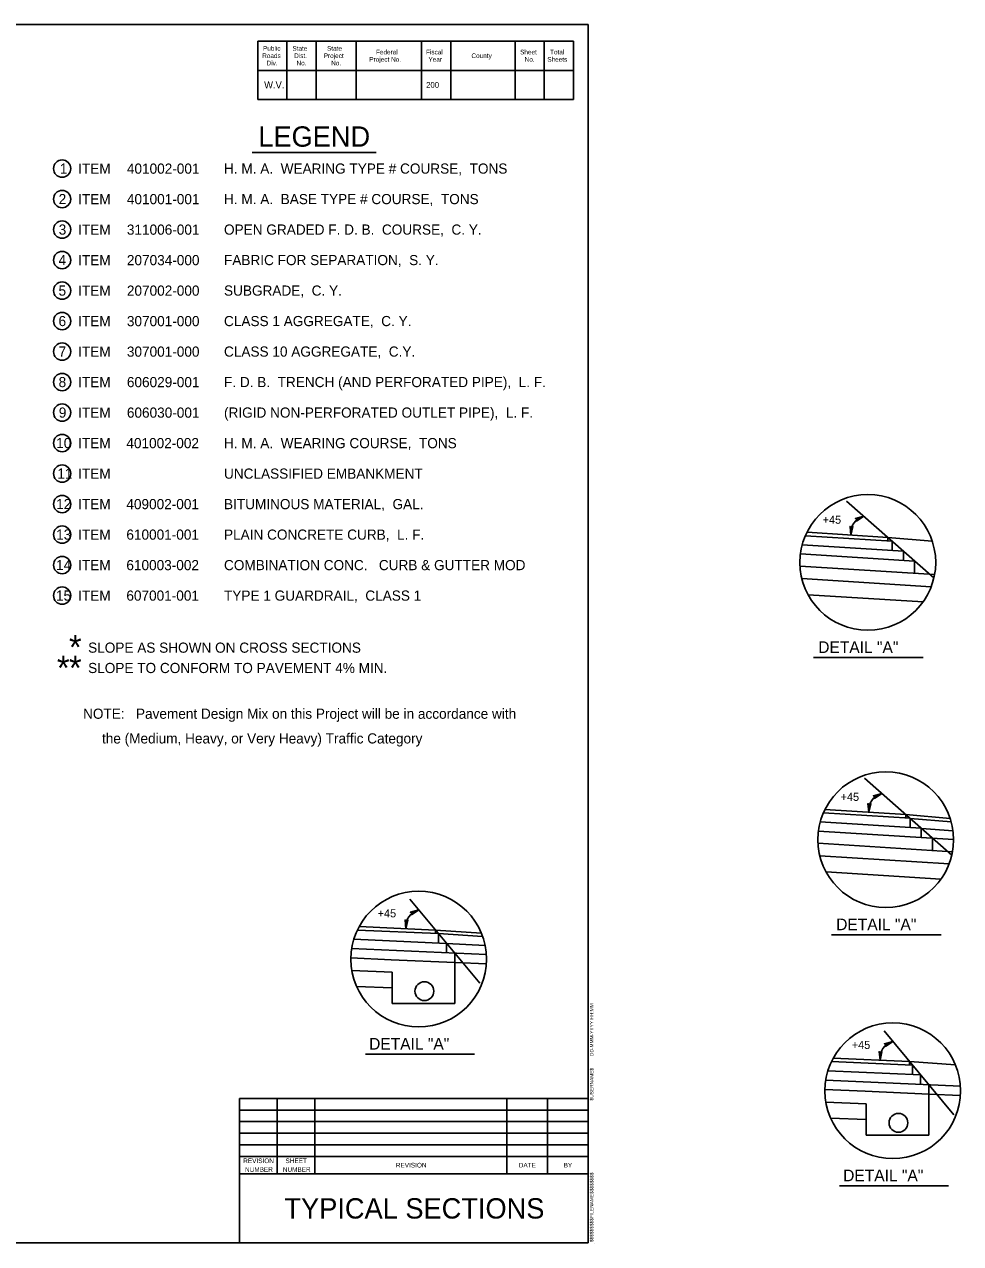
# Model space of a CAD drawing. Extents: x -540 to 1231, y -564 to 421.
# Drawn here: x 115.3 to 276.4, y -562.5 to -352.7 of the extents above; entities that cross this region are included whole.
import ezdxf

# ---------------------------------------------------------------- set-up
doc = ezdxf.new("R2010")
doc.units = 0
doc.layers.add('1', color=7, linetype='Continuous')
doc.layers.add('Des_ Drain_ Ftrs', color=7, linetype='Continuous')

msp = doc.modelspace()

# ---------------------------------------------------------------- linework, layer by layer
at = {"layer": '1'}
for p, q in [((212.32, -352.66), (-107.68, -352.66)), ((212.32, -352.66), (212.32, -562.42)), ((212.32, -352.66), (212.32, -352.66)), ((155.48, -355.54), (155.48, -365.6)), ((209.82, -355.54), (155.48, -355.54)), ((160.51, -355.54), (160.51, -365.6)), ((165.54, -355.54), (165.54, -365.6)), ((172.43, -355.54), (172.43, -365.6)), ((183.65, -355.54), (183.65, -365.6)), ((188.69, -355.54), (188.69, -365.6)), ((199.76, -355.54), (199.76, -365.6)), ((204.79, -355.54), (204.79, -365.6)), ((209.82, -355.54), (209.82, -365.6)), ((209.82, -360.58), (155.48, -360.58)), ((209.82, -365.6), (155.48, -365.6)), ((154.51, -374.73), (175.88, -374.73)), ((271.83, -447.95), (256.82, -434.73)), ((264.63, -441.61), (249.74, -440.68)), ((263.9, -440.97), (250, -440.1)), ((266.58, -443.33), (249.19, -442.23)), ((263.9, -441.57), (263.9, -440.97)), ((271.56, -441.65), (263.9, -440.97)), ((264.63, -441.61), (264.63, -443.21)), ((268.52, -445.04), (248.88, -443.81)), ((266.58, -443.33), (266.58, -444.92)), ((271.95, -447.36), (248.8, -445.9)), ((268.52, -445.04), (268.52, -447.15)), ((271.37, -449.46), (249.12, -448.07)), ((269.96, -452.08), (250.19, -450.84)), ((251.13, -461.65), (269.97, -461.65)), ((274.92, -495.67), (259.9, -482.45)), ((267.72, -489.33), (252.83, -488.39)), ((266.99, -488.69), (253.09, -487.82)), ((266.99, -489.28), (266.99, -488.68)), ((274.64, -489.37), (266.99, -488.68)), ((269.66, -491.05), (252.28, -489.95)), ((267.72, -489.33), (267.72, -490.92)), ((274.81, -489.93), (267.73, -489.34)), ((269.66, -491.05), (269.66, -492.64)), ((275.12, -491.47), (269.69, -491.07)), ((275.22, -492.99), (251.97, -491.53)), ((271.61, -492.76), (271.61, -494.86)), ((275.04, -495.08), (251.89, -493.62)), ((274.45, -497.18), (252.21, -495.78)), ((273.05, -499.8), (253.27, -498.56)), ((193.7, -517.72), (181.68, -503.26)), ((186.57, -509.18), (172.63, -508.57)), ((186.08, -508.56), (172.93, -507.98)), ((186.08, -509.16), (186.08, -508.56)), ((193.97, -509.13), (186.08, -508.56)), ((186.57, -509.18), (186.57, -510.81)), ((194.18, -509.68), (186.57, -509.18)), ((254.22, -509.37), (273.06, -509.37)), ((194.82, -512.77), (171.64, -511.76)), ((187.99, -510.86), (172.01, -510.16)), ((187.98, -510.86), (187.98, -512.47)), ((194.61, -511.22), (187.98, -510.86)), ((178.42, -513.68), (171.5, -513.37)), ((189.39, -514.15), (178.42, -513.68)), ((189.39, -512.54), (189.39, -514.15)), ((189.39, -521.23), (189.39, -514.15)), ((194.82, -514.39), (189.39, -514.15)), ((178.61, -515.84), (171.67, -515.54)), ((178.61, -521.23), (178.61, -515.84)), ((178.61, -515.84), (178.61, -515.84)), ((178.61, -518.54), (172.49, -518.27)), ((178.61, -521.23), (189.39, -521.23)), ((275.27, -540.38), (263.26, -525.92)), ((174.01, -529.94), (192.79, -529.94)), ((267.65, -531.21), (254.5, -530.64)), ((269.56, -533.51), (253.58, -532.82)), ((268.15, -531.83), (254.2, -531.22)), ((267.65, -531.81), (267.65, -531.21)), ((275.55, -531.78), (267.65, -531.21)), ((268.15, -531.83), (268.15, -533.46)), ((276.4, -535.43), (253.22, -534.42)), ((269.55, -533.51), (269.55, -535.12)), ((270.96, -535.19), (270.96, -536.81)), ((259.99, -536.33), (253.08, -536.03)), ((270.96, -536.81), (259.99, -536.33)), ((270.96, -543.89), (270.96, -536.81)), ((276.4, -537.05), (270.96, -536.81)), ((152.32, -562.54), (152.32, -537.55)), ((212.32, -537.55), (152.32, -537.55)), ((158.82, -550.54), (158.82, -537.55)), ((165.33, -550.54), (165.33, -537.55)), ((198.32, -550.54), (198.32, -537.55)), ((205.32, -550.54), (205.32, -537.55)), ((212.32, -562.42), (212.32, -537.55)), ((260.18, -538.5), (253.24, -538.2)), ((260.18, -543.89), (260.18, -538.5)), ((260.18, -538.5), (260.18, -538.5)), ((212.32, -539.55), (152.32, -539.55)), ((260.18, -541.19), (254.06, -540.93)), ((212.32, -541.54), (152.32, -541.54)), ((212.32, -543.55), (152.32, -543.55)), ((212.32, -545.54), (152.32, -545.54)), ((260.18, -543.89), (270.96, -543.89)), ((212.32, -547.54), (152.32, -547.54)), ((212.32, -550.54), (152.32, -550.54)), ((255.58, -552.6), (274.36, -552.6)), ((212.32, -562.42), (-107.68, -562.42)), ((212.32, -562.42), (212.32, -562.42)), ((213.42, -562.54), (213.42, -562.54)), ((213.42, -562.54), (213.42, -562.54))]:
    msp.add_line(p, q, dxfattribs=at)
for centre, radius in [((121.83, -377.49), 1.49), ((121.83, -382.74), 1.49), ((121.83, -387.99), 1.49), ((121.83, -393.24), 1.49), ((121.83, -398.49), 1.49), ((121.83, -403.74), 1.49), ((121.83, -408.99), 1.49), ((121.83, -414.24), 1.49), ((121.83, -419.49), 1.49), ((121.83, -424.74), 1.49), ((121.83, -429.99), 1.49), ((121.83, -435.24), 1.49), ((260.46, -445.29), 11.68), ((121.83, -440.49), 1.49), ((121.83, -445.74), 1.49), ((121.83, -450.99), 1.49), ((263.55, -493.01), 11.68), ((183.18, -513.57), 11.68), ((184.16, -519.09), 1.62), ((264.75, -536.23), 11.68), ((265.73, -541.75), 1.62)]:
    msp.add_circle(centre, radius, dxfattribs=at)
for centre in [(260.41, -440.15), (263.5, -487.87), (183.84, -507.91), (265.42, -530.56)]:
    msp.add_arc(centre, 2.88, 102.7123, 188.5092, dxfattribs=at)
at = {"layer": 'Des_ Drain_ Ftrs'}
for points in [[(259.78, -437.34), (258.53, -438.18), (258.69, -437.83), (258.32, -437.73)], [(257.56, -440.58), (257.4, -439.08), (257.63, -439.38), (257.9, -439.1)], [(260.65, -488.29), (260.49, -486.79), (260.72, -487.1), (260.98, -486.82)], [(262.86, -485.06), (261.61, -485.9), (261.78, -485.55), (261.41, -485.45)], [(183.21, -505.1), (181.96, -505.94), (182.12, -505.59), (181.75, -505.49)], [(180.99, -508.33), (180.83, -506.83), (181.06, -507.14), (181.33, -506.86)], [(264.78, -527.75), (263.53, -528.6), (263.7, -528.25), (263.32, -528.14)], [(262.57, -530.99), (262.4, -529.49), (262.63, -529.8), (262.9, -529.52)]]:
    msp.add_lwpolyline(points, close=True, dxfattribs=at)

# ---------------------------------------------------------------- texts
at = {"layer": '1'}
for s, height, p in [('Public', 0.8, (156.39, -357.2)), ('State', 0.8, (161.45, -357.2)), ('State', 0.8, (167.41, -357.2)), ('Roads', 0.8, (156.25, -358.46)), ('Div.', 0.8, (157, -359.72)), ('Dist.', 0.8, (161.75, -358.46)), ('Project', 0.8, (166.84, -358.46)), ('Project No.', 0.8, (174.68, -359.09)), ('Federal', 0.8, (175.83, -357.83)), ('Fiscal', 0.8, (184.44, -357.83)), ('Year', 0.8, (184.86, -359.09)), ('County', 0.8, (192.26, -358.46)), ('Sheet', 0.8, (200.63, -357.83)), ('No.', 0.8, (201.41, -359.09)), ('Sheets', 0.8, (205.31, -359.09)), ('Total', 0.8, (205.78, -357.83)), ('No.', 0.8, (162.16, -359.72)), ('No.', 0.8, (168.12, -359.72)), ('W.V.', 1.2, (156.59, -363.69)), ('200 ', 1, (184.46, -363.59)), ('LEGEND', 3.5, (155.58, -373.72)), ('1', 1.75, (121.43, -378.36)), ('ITEM', 1.75, (124.58, -378.37)), ('401002-001', 1.75, (132.97, -378.37)), ('H. M. A.  WEARING TYPE # COURSE,  TONS         ', 1.75, (149.68, -378.36)), ('2', 1.75, (121.23, -383.61)), ('ITEM', 1.75, (124.58, -383.62)), ('401001-001', 1.75, (132.97, -383.62)), ('H. M. A.  BASE TYPE # COURSE,  TONS               ', 1.75, (149.68, -383.61)), ('3', 1.75, (121.24, -388.86)), ('ITEM', 1.75, (124.58, -388.87)), ('311006-001', 1.75, (132.97, -388.87)), ('OPEN GRADED F. D. B.  COURSE,  C. Y.         ', 1.75, (149.68, -388.86)), ('4', 1.75, (121.21, -394.11)), ('ITEM', 1.75, (124.58, -394.12)), ('207034-000', 1.75, (132.97, -394.12)), ('FABRIC FOR SEPARATION,  S. Y.             ', 1.75, (149.68, -394.11)), ('5', 1.75, (121.21, -399.36)), ('ITEM', 1.75, (124.58, -399.37)), ('207002-000', 1.75, (132.97, -399.37)), ('SUBGRADE,  C. Y.                         ', 1.75, (149.68, -399.36)), ('6', 1.75, (121.21, -404.61)), ('ITEM', 1.75, (124.58, -404.62)), ('307001-000', 1.75, (132.97, -404.62)), ('CLASS 1 AGGREGATE,  C. Y.               ', 1.75, (149.68, -404.61)), ('7', 1.75, (121.22, -409.86)), ('ITEM', 1.75, (124.58, -409.87)), ('307001-000', 1.75, (132.97, -409.87)), ('CLASS 10 AGGREGATE,  C.Y.                 ', 1.75, (149.68, -409.86)), ('8', 1.75, (121.22, -415.11)), ('ITEM', 1.75, (124.58, -415.12)), ('606029-001', 1.75, (132.97, -415.12)), ('F. D. B.  TRENCH (AND PERFORATED PIPE),  L. F.', 1.75, (149.68, -415.11)), ('9', 1.75, (121.25, -420.36)), ('ITEM', 1.75, (124.58, -420.37)), ('606030-001', 1.75, (132.97, -420.37)), ('(RIGID NON-PERFORATED OUTLET PIPE),  L. F.  ', 1.75, (149.68, -420.36)), ('10', 1.75, (120.8, -425.61)), ('ITEM', 1.75, (124.58, -425.62)), ('401002-002', 1.75, (132.88, -425.62)), ('H. M. A.  WEARING COURSE,  TONS    ', 1.75, (149.68, -425.62)), ('11', 1.75, (120.99, -430.86)), ('ITEM', 1.75, (124.58, -430.87)), ('UNCLASSIFIED EMBANKMENT              ', 1.75, (149.68, -430.87)), ('12', 1.75, (120.8, -436.11)), ('ITEM', 1.75, (124.58, -436.12)), ('409002-001', 1.75, (132.88, -436.12)), ('BITUMINOUS MATERIAL,  GAL.           ', 1.75, (149.68, -436.12)), ('+45', 1.4, (252.69, -438.63)), ('13', 1.75, (120.8, -441.36)), ('ITEM', 1.75, (124.58, -441.37)), ('610001-001', 1.75, (132.88, -441.37)), ('PLAIN CONCRETE CURB,  L. F.          ', 1.75, (149.68, -441.37)), ('14', 1.75, (120.78, -446.61)), ('ITEM', 1.75, (124.58, -446.62)), ('610003-002', 1.75, (132.88, -446.62)), ('COMBINATION CONC.   CURB & GUTTER MOD', 1.75, (149.68, -446.62)), ('15', 1.75, (120.77, -451.86)), ('ITEM', 1.75, (124.58, -451.87)), ('607001-001', 1.75, (132.88, -451.87)), ('TYPE 1 GUARDRAIL,  CLASS 1           ', 1.75, (149.68, -451.87)), ('SLOPE AS SHOWN ON CROSS SECTIONS', 1.75, (126.3, -460.83)), ('DETAIL "A"', 2, (251.93, -460.87)), ('SLOPE TO CONFORM TO PAVEMENT 4% MIN.', 1.75, (126.3, -464.33)), ('NOTE:   Pavement Design Mix on this Project will be in accordance with', 1.75, (125.43, -472.2)), ('     the (Medium, Heavy, or Very Heavy) Traffic Category', 1.75, (125.43, -476.45)), ('+45', 1.4, (255.78, -486.34)), ('+45', 1.4, (176.12, -506.38)), ('DETAIL "A"', 2, (255.02, -508.59)), ('DETAIL "A"', 2, (174.65, -529.15)), ('+45', 1.4, (257.7, -529.04)), ('REVISION', 0.8, (152.99, -548.69)), ('NUMBER', 0.8, (153.3, -550.19)), ('NUMBER', 0.8, (159.8, -550.19)), ('SHEET', 0.8, (160.26, -548.69)), ('REVISION', 0.8, (179.25, -549.44)), ('DATE', 0.8, (200.4, -549.44)), ('BY', 0.8, (208.12, -549.44)), ('DETAIL "A"', 2, (256.22, -551.81)), ('TYPICAL SECTIONS', 3.5, (160.08, -558.23))]:
    msp.add_text(s, height=height, dxfattribs=at).set_placement(p)
for s, height, rotation, p in [('*', 4.2, 359.9827, (123, -461.97)), ('*', 4.2, 359.9827, (120.93, -465.54)), ('*', 4.2, 359.9827, (123, -465.54)), ('DD-MMM-YYYY HH:MM', 0.6, 90, (213.24, -530.25)), ('$USERNAME$', 0.6, 90, (213.24, -537.9)), ('$$$$$$$$$FILENAME$$$$$$$$', 0.6, 90, (213.24, -562.29))]:
    msp.add_text(s, height=height, rotation=rotation, dxfattribs=at).set_placement(p)

doc.saveas('drawing.dxf')
